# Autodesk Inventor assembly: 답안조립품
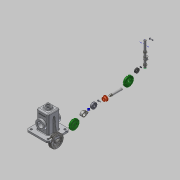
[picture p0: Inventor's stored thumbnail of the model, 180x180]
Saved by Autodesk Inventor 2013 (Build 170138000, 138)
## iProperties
Created: 2016-02
Part Number: 답안조립품
Document SubType Name: Assembly
Designer: dgall
Author: dgall
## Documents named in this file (16)
- C:\Users\dgall\Desktop\460211V1002\답안조립품.iam
- C:\Users\dgall\Desktop\460211V1002\본체.ipt
- C:\Users\dgall\Desktop\460211V1002\V벨트풀리.ipt
- C:\Users\dgall\Desktop\460211V1002\고정핀 1.2 x 10.ipt
- C:\Users\dgall\Desktop\460211V1002\뒤커버.ipt
- C:\Users\dgall\Desktop\460211V1002\링크.ipt
- C:\Users\dgall\Desktop\460211V1002\멈춤나사 M3x8.ipt
- C:\Users\dgall\Desktop\460211V1002\베어링 12 x 32 x 10.ipt
- C:\Users\dgall\Desktop\460211V1002\볼트 M4 x 12.ipt
- C:\Users\dgall\Desktop\460211V1002\부시.ipt
- C:\Users\dgall\Desktop\460211V1002\슬라이드.ipt
- C:\Users\dgall\Desktop\460211V1002\앞커버.ipt
- C:\Users\dgall\Desktop\460211V1002\오일실 12 25 7.ipt
- C:\Users\dgall\Desktop\460211V1002\키 4 x 4 x 10.ipt
- C:\Users\dgall\Desktop\460211V1002\편심축.ipt
- C:\Users\dgall\Desktop\460211V1002\핀 5 x 18.ipt
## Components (4 placed, 4 different names)
1. V벨트풀리:1
2. 고정핀 1.2 x 10:1
3. ISO 4762 M4 x 12:1
4. 핀 5 x 18:1
